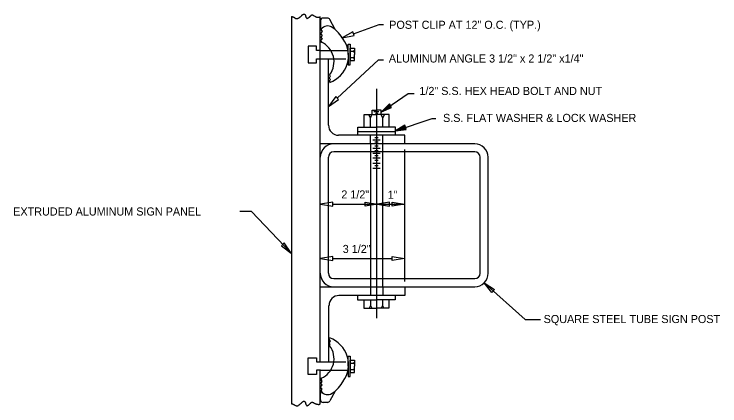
# Model space of a CAD drawing. Extents: x 126.99 to 133.44, y 121.5 to 131.07.
# Drawn here: x 126.99 to 132.24, y 128.16 to 131.07 of the extents above; entities that cross this region are included whole.
import ezdxf

# ---------------------------------------------------------------- set-up
doc = ezdxf.new("R2010")
doc.units = 0
for name, color, linetype in [('DETL-DIMS', 7, 'Continuous'), ('DETL-LINE', 7, 'Continuous'), ('DETL-NOTE', 7, 'Continuous')]:
    doc.layers.add(name, color=color, linetype=linetype)

msp = doc.modelspace()

# ---------------------------------------------------------------- linework, layer by layer
at = {"layer": 'DETL-DIMS'}
for p, q in [((129.5147, 130.9229), (129.7057, 130.9919)), ((129.7057, 130.9919), (129.7367, 130.9919)), ((129.3937, 130.4449), (129.7007, 130.7299)), ((129.7007, 130.7299), (129.7367, 130.7299)), ((129.6847, 130.5129), (129.6847, 128.8109)), ((129.7217, 130.3439), (129.9207, 130.4799)), ((129.9207, 130.4799), (129.9647, 130.4799)), ((129.8257, 130.2029), (130.0997, 130.2929)), ((130.0997, 130.2929), (130.1257, 130.2929)), ((129.8927, 130.0639), (129.8927, 129.0839)), ((129.3597, 129.6575), (129.8927, 129.6575)), ((129.3597, 129.2549), (129.7607, 129.2549)), ((129.7607, 129.2549), (129.8007, 129.2549))]:
    msp.add_line(p, q, dxfattribs=at)
for points in [[(129.5197, 130.9089), (129.5097, 130.9369), (129.4307, 130.8929)], [(129.4037, 130.4339), (129.3827, 130.4559), (129.3277, 130.3829)], [(129.3597, 129.6425), (129.3597, 129.6725), (129.2697, 129.6575)], [(129.6018, 129.6425), (129.6018, 129.6725), (129.6918, 129.6575)], [(129.7818, 129.6425), (129.7818, 129.6725), (129.6918, 129.6575)], [(129.8027, 129.6425), (129.8027, 129.6725), (129.8927, 129.6575)], [(129.0002, 129.3701), (128.9784, 129.3494), (129.0512, 129.2945)], [(129.3597, 129.2399), (129.3597, 129.2699), (129.2697, 129.2549)], [(129.8027, 129.2399), (129.8027, 129.2699), (129.8927, 129.2549)], [(130.5624, 129.0252), (130.5424, 129.0029), (130.4854, 129.0742)]]:
    msp.add_lwpolyline(points, close=True, dxfattribs=at)
for points in [[(129.7807, 130.4019), (129.7217, 130.3439), (129.7977, 130.3759), (129.7807, 130.4019)], [(129.7797, 130.3989), (129.7307, 130.3499), (129.7947, 130.3769), (129.7797, 130.3989)], [(129.7797, 130.3959), (129.7397, 130.3559), (129.7917, 130.3779), (129.7797, 130.3959)], [(129.7797, 130.3929), (129.7477, 130.3609), (129.7887, 130.3789), (129.7797, 130.3929)], [(129.7787, 130.3899), (129.7567, 130.3679), (129.7857, 130.3799), (129.7787, 130.3899)], [(129.7787, 130.3869), (129.7657, 130.3739), (129.7827, 130.3809), (129.7787, 130.3869)], [(129.7787, 130.3839), (129.7747, 130.3799), (129.7797, 130.3809), (129.7787, 130.3839)], [(129.8967, 130.2429), (129.8257, 130.2029), (129.9067, 130.2129), (129.8967, 130.2429)], [(129.8957, 130.2409), (129.8357, 130.2059), (129.9047, 130.2149), (129.8957, 130.2409)], [(129.8957, 130.2369), (129.8457, 130.2099), (129.9017, 130.2159), (129.8957, 130.2369)], [(129.8937, 130.2349), (129.8557, 130.2129), (129.8997, 130.2189), (129.8937, 130.2349)], [(129.8927, 130.2309), (129.8657, 130.2159), (129.8957, 130.2209), (129.8927, 130.2309)], [(129.8917, 130.2289), (129.8757, 130.2199), (129.8937, 130.2219), (129.8917, 130.2289)], [(129.8907, 130.2259), (129.8857, 130.2229), (129.8907, 130.2229), (129.8907, 130.2259)], [(129.0506, 129.295), (128.756, 129.6034), (128.671, 129.6034)], [(130.4854, 129.0742), (130.7888, 128.8012), (130.9022, 128.8012)]]:
    msp.add_lwpolyline(points, dxfattribs=at)
at = {"layer": 'DETL-LINE'}
for p, q in [((129.0527, 131.0499), (129.0527, 128.1759)), ((129.0527, 131.0499), (129.0607, 131.0499)), ((129.0607, 131.0499), (129.0607, 131.0489)), ((129.0607, 131.0489), (129.0637, 131.0489)), ((129.0637, 131.0489), (129.0647, 131.0469)), ((129.0647, 131.0469), (129.0677, 131.0469)), ((129.0677, 131.0469), (129.0687, 131.0459)), ((129.0687, 131.0459), (129.0697, 131.0449)), ((129.0697, 131.0449), (129.0707, 131.0449)), ((129.0707, 131.0449), (129.0727, 131.0449)), ((129.0727, 131.0449), (129.0737, 131.0429)), ((129.0737, 131.0429), (129.0757, 131.0409)), ((129.1097, 131.0409), (129.1107, 131.0429)), ((129.1107, 131.0429), (129.1127, 131.0429)), ((129.1127, 131.0429), (129.1147, 131.0449)), ((129.1147, 131.0449), (129.1157, 131.0449)), ((129.1157, 131.0459), (129.1197, 131.0479)), ((129.1157, 131.0449), (129.1157, 131.0459)), ((129.1197, 131.0479), (129.1207, 131.0499)), ((129.1207, 131.0499), (129.1207, 131.0509)), ((129.1207, 131.0509), (129.1227, 131.0509)), ((129.1227, 131.0509), (129.1267, 131.0559)), ((129.1267, 131.0559), (129.1277, 131.0559)), ((129.1277, 131.0559), (129.1297, 131.0579)), ((129.1297, 131.0579), (129.1307, 131.0599)), ((129.1307, 131.0599), (129.1307, 131.0609)), ((129.1307, 131.0609), (129.1317, 131.0609)), ((129.1317, 131.0609), (129.1327, 131.0619)), ((129.1327, 131.0619), (129.1347, 131.0629)), ((129.1347, 131.0629), (129.1357, 131.0649)), ((129.1357, 131.0649), (129.1377, 131.0659)), ((129.1377, 131.0659), (129.1397, 131.0659)), ((129.1397, 131.0659), (129.1427, 131.0679)), ((129.1427, 131.0679), (129.1437, 131.0679)), ((129.1437, 131.0679), (129.1457, 131.0679)), ((129.1457, 131.0679), (129.1487, 131.0679)), ((129.1487, 131.0679), (129.1497, 131.0679)), ((129.1497, 131.0679), (129.1507, 131.0669)), ((129.1507, 131.0669), (129.1527, 131.0659)), ((129.1527, 131.0659), (129.1537, 131.0649)), ((129.1537, 131.0649), (129.1547, 131.0649)), ((129.1547, 131.0649), (129.1557, 131.0609)), ((129.1557, 131.0609), (129.1577, 131.0599)), ((129.1577, 131.0599), (129.1577, 131.0579)), ((129.1577, 131.0579), (129.1577, 131.0559)), ((129.1577, 131.0559), (129.1577, 131.0549)), ((129.1577, 131.0549), (129.1587, 131.0529)), ((129.1587, 131.0529), (129.1587, 131.0509)), ((129.1587, 131.0509), (129.1597, 131.0509)), ((129.1597, 131.0509), (129.1597, 131.0499)), ((129.1597, 131.0499), (129.1607, 131.0449)), ((129.1607, 131.0449), (129.1607, 131.0449)), ((129.1607, 131.0449), (129.1627, 131.0429)), ((129.1627, 131.0429), (129.1627, 131.0419)), ((129.1627, 131.0419), (129.1647, 131.0399)), ((129.1797, 131.0409), (129.1827, 131.0429)), ((129.1827, 131.0429), (129.1847, 131.0449)), ((129.1847, 131.0449), (129.1857, 131.0459)), ((129.1857, 131.0459), (129.1867, 131.0459)), ((129.1867, 131.0459), (129.1907, 131.0509)), ((129.1907, 131.0509), (129.1917, 131.0509)), ((129.1917, 131.0509), (129.1927, 131.0529)), ((129.1927, 131.0529), (129.1947, 131.0529)), ((129.1947, 131.0529), (129.1957, 131.0549)), ((129.1957, 131.0549), (129.1977, 131.0559)), ((129.1977, 131.0559), (129.2007, 131.0589)), ((129.2007, 131.0609), (129.2057, 131.0619)), ((129.2007, 131.0599), (129.2007, 131.0609)), ((129.2007, 131.0589), (129.2007, 131.0599)), ((129.2057, 131.0619), (129.2097, 131.0619)), ((129.2097, 131.0619), (129.2127, 131.0609)), ((129.2127, 131.0609), (129.2147, 131.0609)), ((129.2147, 131.0609), (129.2147, 131.0599)), ((129.2147, 131.0599), (129.2177, 131.0589)), ((129.2177, 131.0589), (129.2197, 131.0569)), ((129.2197, 131.0569), (129.2207, 131.0559)), ((129.2207, 131.0559), (129.2207, 131.0559)), ((129.2207, 131.0559), (129.2227, 131.0559)), ((129.2227, 131.0559), (129.2277, 131.0529)), ((129.2277, 131.0529), (129.2297, 131.0529)), ((129.2297, 131.0529), (129.2297, 131.0509)), ((129.2297, 131.0509), (129.2307, 131.0509)), ((129.2307, 131.0509), (129.2327, 131.0509)), ((129.2327, 131.0509), (129.2347, 131.0499)), ((129.2347, 131.0499), (129.2357, 131.0499)), ((129.2357, 131.0499), (129.2357, 131.0489)), ((129.2357, 131.0489), (129.2377, 131.0489)), ((129.2377, 131.0489), (129.2387, 131.0469)), ((129.2387, 131.0469), (129.2407, 131.0469)), ((129.2407, 131.0469), (129.2407, 131.0459)), ((129.2407, 131.0459), (129.2507, 131.0459)), ((129.2507, 131.0459), (129.2527, 131.0459)), ((129.2527, 131.0459), (129.2587, 131.0459)), ((129.2587, 131.0459), (129.2607, 131.0459)), ((129.2607, 131.0459), (129.2637, 131.0459)), ((129.2637, 131.0459), (129.2677, 131.0499)), ((129.2677, 128.4879), (129.2677, 131.0499)), ((129.0757, 131.0409), (129.0777, 131.0409)), ((129.0777, 131.0409), (129.0847, 131.0359)), ((129.0847, 131.0359), (129.0857, 131.0359)), ((129.0857, 131.0359), (129.0877, 131.0359)), ((129.0877, 131.0359), (129.0897, 131.0359)), ((129.0897, 131.0359), (129.0907, 131.0349)), ((129.0907, 131.0349), (129.0997, 131.0349)), ((129.0997, 131.0349), (129.0997, 131.0359)), ((129.0997, 131.0359), (129.1007, 131.0359)), ((129.1007, 131.0359), (129.1027, 131.0369)), ((129.1027, 131.0379), (129.1047, 131.0389)), ((129.1027, 131.0369), (129.1027, 131.0379)), ((129.1047, 131.0389), (129.1057, 131.0399)), ((129.1057, 131.0399), (129.1097, 131.0409)), ((129.1647, 131.0399), (129.1657, 131.0389)), ((129.1657, 131.0389), (129.1657, 131.0379)), ((129.1657, 131.0379), (129.1667, 131.0369)), ((129.1667, 131.0369), (129.1687, 131.0359)), ((129.1687, 131.0359), (129.1707, 131.0359)), ((129.1707, 131.0359), (129.1747, 131.0379)), ((129.1747, 131.0379), (129.1757, 131.0389)), ((129.1757, 131.0389), (129.1777, 131.0399)), ((129.1777, 131.0399), (129.1777, 131.0409)), ((129.1777, 131.0409), (129.1797, 131.0409)), ((129.2688, 131.0185), (129.2688, 130.9714)), ((129.3208, 131.0382), (129.289, 131.0385)), ((129.3778, 130.9541), (129.3382, 131.0277)), ((129.2807, 130.9399), (129.2697, 130.9239)), ((129.2703, 130.9639), (129.2738, 130.9553)), ((129.2727, 130.9549), (129.2807, 130.9399)), ((129.2697, 130.9239), (129.2807, 130.9079)), ((129.2807, 130.9079), (129.2707, 130.8959)), ((129.2707, 130.8959), (129.2807, 130.8819)), ((129.2807, 130.8819), (129.2697, 130.8729)), ((129.2697, 130.8729), (129.2787, 130.8659)), ((129.2787, 130.8659), (129.2727, 130.8599)), ((129.4757, 130.8459), (129.4907, 130.8459)), ((129.4757, 130.7689), (129.4757, 130.8459)), ((129.4907, 130.8459), (129.4907, 130.7689)), ((129.1777, 130.8299), (129.1777, 130.7059)), ((129.2397, 130.8299), (129.1777, 130.8299)), ((129.2397, 130.7989), (129.2397, 130.8299)), ((129.2697, 130.7989), (129.2397, 130.7989)), ((129.2697, 130.7989), (129.3507, 130.7989)), ((129.3507, 130.7989), (129.4757, 130.7989)), ((129.4907, 130.8149), (129.5227, 130.8149)), ((129.4907, 130.7689), (129.4907, 130.8149)), ((129.4907, 130.7929), (129.5107, 130.7929)), ((129.4907, 130.7929), (129.5107, 130.7929)), ((129.5107, 130.7929), (129.5217, 130.7999)), ((129.5107, 130.7929), (129.5217, 130.7859)), ((129.5227, 130.8149), (129.5227, 130.7689)), ((129.2397, 130.7359), (129.3647, 130.7359)), ((129.2397, 130.7059), (129.2397, 130.7359)), ((129.3277, 130.2439), (129.3277, 130.7359)), ((129.3647, 130.7359), (129.4577, 130.7359)), ((129.4757, 130.7689), (129.4757, 130.6929)), ((129.4907, 130.6929), (129.4907, 130.7689)), ((129.4907, 130.7689), (129.4907, 130.7229)), ((129.4907, 130.7449), (129.5107, 130.7449)), ((129.4907, 130.7449), (129.5107, 130.7449)), ((129.5107, 130.7449), (129.5217, 130.7509)), ((129.5107, 130.7449), (129.5217, 130.7379)), ((129.5227, 130.7229), (129.5227, 130.7689)), ((129.1777, 130.7059), (129.2397, 130.7059)), ((129.4757, 130.6929), (129.4907, 130.6929)), ((129.4907, 130.7229), (129.5227, 130.7229)), ((129.3427, 130.5829), (129.3327, 130.5729)), ((129.3327, 130.5729), (129.3397, 130.5659)), ((129.3407, 130.6079), (129.3347, 130.5939)), ((129.3347, 130.5939), (129.3427, 130.5829)), ((129.3357, 130.6179), (129.3407, 130.6079)), ((129.3397, 130.5659), (129.3357, 130.5599)), ((129.5927, 130.2299), (129.5927, 130.3229)), ((129.5927, 130.3229), (129.6857, 130.3229)), ((129.6397, 130.2949), (129.6277, 130.3229)), ((129.6397, 130.2949), (129.6507, 130.3229)), ((129.6537, 130.3229), (129.6537, 130.3549)), ((129.6537, 130.3549), (129.6857, 130.3549)), ((129.6657, 130.3449), (129.7027, 130.3449)), ((129.6777, 130.3329), (129.6947, 130.3329)), ((129.7187, 130.3549), (129.6857, 130.3549)), ((129.7797, 130.3229), (129.6857, 130.3229)), ((129.7187, 130.3229), (129.7187, 130.3549)), ((129.7327, 130.2949), (129.7207, 130.3229)), ((129.7327, 130.2949), (129.7437, 130.3229)), ((129.7797, 130.2299), (129.7797, 130.3229)), ((129.6397, 130.2609), (129.6397, 130.2949)), ((129.6397, 130.2299), (129.6397, 130.2609)), ((129.7327, 130.2609), (129.7327, 130.2949)), ((129.7327, 130.2299), (129.7327, 130.2609)), ((129.5457, 130.1689), (129.5457, 130.2299)), ((129.5457, 130.2299), (129.6857, 130.2299)), ((129.8257, 130.2299), (129.6857, 130.2299)), ((129.8257, 130.1689), (129.8257, 130.2299)), ((129.8947, 130.1689), (129.4027, 130.1689)), ((129.5457, 130.1969), (129.8257, 130.1969)), ((129.6397, 130.1069), (129.6397, 130.1689)), ((129.6727, 130.1529), (129.6977, 130.1529)), ((129.7327, 130.1069), (129.7327, 130.1689)), ((129.8947, 130.1069), (129.8947, 130.1689)), ((130.4147, 130.1059), (129.2677, 130.1059)), ((129.6397, 130.1069), (129.6397, 129.0439)), ((129.6577, 130.1359), (129.7127, 130.1359)), ((129.6727, 130.1199), (129.6977, 130.1199)), ((129.7327, 129.0439), (129.7327, 130.1069)), ((130.4147, 130.0459), (129.3677, 130.0459)), ((129.6577, 130.0729), (129.7127, 130.0729)), ((129.6727, 130.0899), (129.6977, 130.0899)), ((129.6727, 130.0549), (129.6977, 130.0549)), ((129.3277, 129.1449), (129.3277, 130.0059)), ((129.6577, 130.0359), (129.7127, 130.0359)), ((129.6577, 130.0009), (129.7127, 130.0009)), ((129.6727, 130.0199), (129.6977, 130.0199)), ((130.4547, 129.1449), (130.4547, 130.0059)), ((130.5147, 129.1449), (130.5147, 130.0059)), ((129.6577, 129.9629), (129.7127, 129.9629)), ((129.6727, 129.9849), (129.6977, 129.9849)), ((129.6727, 129.9449), (129.6977, 129.9449)), ((129.6577, 129.9249), (129.7127, 129.9249)), ((129.3677, 129.1049), (130.4147, 129.1049)), ((129.2677, 129.0449), (130.4147, 129.0449)), ((129.6397, 129.0439), (129.6397, 128.9779)), ((129.7327, 129.0439), (129.7327, 128.9779)), ((129.8947, 129.0449), (129.8947, 128.9799)), ((129.8947, 128.9799), (129.4057, 128.9799)), ((129.5447, 128.9789), (129.5447, 128.9479)), ((129.5447, 128.9479), (129.6847, 128.9479)), ((129.5907, 128.9479), (129.5907, 128.8859)), ((129.6397, 128.9479), (129.6397, 128.9059)), ((129.8247, 128.9479), (129.6847, 128.9479)), ((129.7297, 128.9479), (129.7297, 128.9059)), ((129.7777, 128.9479), (129.7777, 128.8859)), ((129.8247, 128.9789), (129.8247, 128.9479)), ((129.3307, 128.4859), (129.3307, 128.9049)), ((129.6397, 128.9059), (129.6297, 128.8859)), ((129.6397, 128.9059), (129.6497, 128.8859)), ((129.7297, 128.9059), (129.7187, 128.8859)), ((129.7297, 128.9059), (129.7397, 128.8859)), ((129.5907, 128.8859), (129.6847, 128.8859)), ((129.7777, 128.8859), (129.6847, 128.8859)), ((129.3327, 128.6509), (129.3397, 128.6579)), ((129.3427, 128.6409), (129.3327, 128.6509)), ((129.3347, 128.6299), (129.3427, 128.6409)), ((129.3407, 128.6159), (129.3347, 128.6299)), ((129.3397, 128.6579), (129.3357, 128.6649)), ((129.3357, 128.6059), (129.3407, 128.6159)), ((129.4757, 128.5309), (129.4907, 128.5309)), ((129.4757, 128.4549), (129.4757, 128.5309)), ((129.4907, 128.5309), (129.4907, 128.4549)), ((129.1777, 128.3949), (129.1777, 128.5179)), ((129.1777, 128.5179), (129.2397, 128.5179)), ((129.2397, 128.5179), (129.2397, 128.4879)), ((129.2397, 128.4879), (129.3647, 128.4879)), ((129.3647, 128.4879), (129.4577, 128.4879)), ((129.4907, 128.5009), (129.5227, 128.5009)), ((129.4907, 128.4549), (129.4907, 128.5009)), ((129.4907, 128.4789), (129.5107, 128.4789)), ((129.4907, 128.4789), (129.5107, 128.4789)), ((129.5107, 128.4789), (129.5217, 128.4849)), ((129.5107, 128.4789), (129.5217, 128.4729)), ((129.5227, 128.5009), (129.5227, 128.4549)), ((129.2697, 128.4249), (129.2397, 128.4249)), ((129.2397, 128.4249), (129.2397, 128.3949)), ((129.2677, 128.1759), (129.2677, 128.4249)), ((129.2697, 128.4249), (129.3507, 128.4249)), ((129.3507, 128.4249), (129.4757, 128.4249)), ((129.4757, 128.4549), (129.4757, 128.3779)), ((129.4907, 128.3779), (129.4907, 128.4549)), ((129.4907, 128.4549), (129.4907, 128.4089)), ((129.4907, 128.4309), (129.5107, 128.4309)), ((129.4907, 128.4309), (129.5107, 128.4309)), ((129.5107, 128.4309), (129.5217, 128.4369)), ((129.5107, 128.4309), (129.5217, 128.4249)), ((129.5227, 128.4089), (129.5227, 128.4549)), ((129.2397, 128.3949), (129.1777, 128.3949)), ((129.4757, 128.3779), (129.4907, 128.3779)), ((129.4907, 128.4089), (129.5227, 128.4089)), ((129.2697, 128.3509), (129.2787, 128.3559)), ((129.2807, 128.3409), (129.2697, 128.3509)), ((129.2697, 128.2999), (129.2807, 128.3159)), ((129.2707, 128.3279), (129.2807, 128.3409)), ((129.2807, 128.3159), (129.2707, 128.3279)), ((129.2787, 128.3559), (129.2727, 128.3649)), ((129.2807, 128.2849), (129.2697, 128.2999)), ((129.2703, 128.2613), (129.2738, 128.2699)), ((129.2727, 128.2699), (129.2807, 128.2849)), ((129.3778, 128.271), (129.3382, 128.1975)), ((129.2688, 128.2067), (129.2688, 128.2537)), ((129.0527, 128.1759), (129.0607, 128.1759)), ((129.0607, 128.1759), (129.0607, 128.1749)), ((129.0607, 128.1749), (129.0637, 128.1749)), ((129.0637, 128.1749), (129.0647, 128.1729)), ((129.0647, 128.1729), (129.0677, 128.1729)), ((129.0677, 128.1729), (129.0687, 128.1729)), ((129.0687, 128.1729), (129.0697, 128.1709)), ((129.0697, 128.1709), (129.0707, 128.1709)), ((129.0707, 128.1709), (129.0727, 128.1699)), ((129.0727, 128.1699), (129.0737, 128.1689)), ((129.0737, 128.1689), (129.0757, 128.1679)), ((129.0757, 128.1679), (129.0777, 128.1659)), ((129.0777, 128.1659), (129.0847, 128.1629)), ((129.0847, 128.1629), (129.0857, 128.1629)), ((129.0857, 128.1629), (129.0877, 128.1609)), ((129.0877, 128.1609), (129.0897, 128.1609)), ((129.0897, 128.1609), (129.0907, 128.1609)), ((129.0907, 128.1609), (129.0997, 128.1609)), ((129.0997, 128.1609), (129.1007, 128.1609)), ((129.0997, 128.1609), (129.0997, 128.1609)), ((129.1007, 128.1609), (129.1027, 128.1629)), ((129.1027, 128.1639), (129.1047, 128.1649)), ((129.1027, 128.1629), (129.1027, 128.1639)), ((129.1047, 128.1649), (129.1057, 128.1659)), ((129.1057, 128.1659), (129.1097, 128.1679)), ((129.1097, 128.1679), (129.1107, 128.1689)), ((129.1107, 128.1689), (129.1127, 128.1699)), ((129.1127, 128.1699), (129.1147, 128.1709)), ((129.1147, 128.1709), (129.1157, 128.1709)), ((129.1157, 128.1729), (129.1197, 128.1749)), ((129.1157, 128.1709), (129.1157, 128.1729)), ((129.1197, 128.1749), (129.1207, 128.1759)), ((129.1207, 128.1759), (129.1227, 128.1779)), ((129.1207, 128.1759), (129.1207, 128.1759)), ((129.1227, 128.1779), (129.1267, 128.1809)), ((129.1267, 128.1809), (129.1277, 128.1829)), ((129.1277, 128.1829), (129.1297, 128.1839)), ((129.1297, 128.1839), (129.1307, 128.1859)), ((129.1307, 128.1859), (129.1317, 128.1869)), ((129.1307, 128.1859), (129.1307, 128.1859)), ((129.1317, 128.1869), (129.1327, 128.1879)), ((129.1327, 128.1879), (129.1347, 128.1899)), ((129.1347, 128.1899), (129.1357, 128.1909)), ((129.1357, 128.1909), (129.1377, 128.1909)), ((129.1377, 128.1909), (129.1397, 128.1929)), ((129.1397, 128.1929), (129.1427, 128.1949)), ((129.1427, 128.1949), (129.1437, 128.1949)), ((129.1437, 128.1949), (129.1457, 128.1949)), ((129.1457, 128.1949), (129.1487, 128.1949)), ((129.1487, 128.1949), (129.1497, 128.1949)), ((129.1497, 128.1949), (129.1507, 128.1929)), ((129.1507, 128.1929), (129.1527, 128.1909)), ((129.1527, 128.1909), (129.1537, 128.1909)), ((129.1537, 128.1909), (129.1547, 128.1909)), ((129.1547, 128.1909), (129.1557, 128.1859)), ((129.1557, 128.1859), (129.1577, 128.1859)), ((129.1577, 128.1859), (129.1577, 128.1839)), ((129.1577, 128.1839), (129.1577, 128.1829)), ((129.1577, 128.1829), (129.1577, 128.1809)), ((129.1577, 128.1809), (129.1587, 128.1799)), ((129.1587, 128.1799), (129.1587, 128.1779)), ((129.1587, 128.1779), (129.1597, 128.1759)), ((129.1597, 128.1759), (129.1607, 128.1709)), ((129.1597, 128.1759), (129.1597, 128.1759)), ((129.1607, 128.1709), (129.1607, 128.1699)), ((129.1607, 128.1699), (129.1627, 128.1689)), ((129.1627, 128.1689), (129.1627, 128.1679)), ((129.1627, 128.1679), (129.1647, 128.1659)), ((129.1647, 128.1659), (129.1657, 128.1649)), ((129.1657, 128.1649), (129.1657, 128.1639)), ((129.1657, 128.1639), (129.1667, 128.1629)), ((129.1667, 128.1629), (129.1687, 128.1609)), ((129.1687, 128.1609), (129.1707, 128.1609)), ((129.1707, 128.1609), (129.1747, 128.1639)), ((129.1747, 128.1639), (129.1757, 128.1649)), ((129.1757, 128.1649), (129.1777, 128.1659)), ((129.1777, 128.1669), (129.1797, 128.1669)), ((129.1777, 128.1659), (129.1777, 128.1669)), ((129.1797, 128.1669), (129.1827, 128.1699)), ((129.1827, 128.1699), (129.1847, 128.1709)), ((129.1847, 128.1709), (129.1857, 128.1709)), ((129.1857, 128.1709), (129.1867, 128.1729)), ((129.1867, 128.1729), (129.1907, 128.1759)), ((129.1907, 128.1759), (129.1917, 128.1779)), ((129.1917, 128.1779), (129.1927, 128.1789)), ((129.1927, 128.1789), (129.1947, 128.1799)), ((129.1947, 128.1799), (129.1957, 128.1809)), ((129.1957, 128.1809), (129.1977, 128.1819)), ((129.1977, 128.1819), (129.2007, 128.1849)), ((129.2007, 128.1859), (129.2057, 128.1879)), ((129.2007, 128.1859), (129.2007, 128.1859)), ((129.2007, 128.1849), (129.2007, 128.1859)), ((129.2057, 128.1879), (129.2097, 128.1879)), ((129.2097, 128.1879), (129.2127, 128.1869)), ((129.2127, 128.1869), (129.2147, 128.1859)), ((129.2147, 128.1859), (129.2177, 128.1849)), ((129.2147, 128.1859), (129.2147, 128.1859)), ((129.2177, 128.1849), (129.2197, 128.1829)), ((129.2197, 128.1829), (129.2207, 128.1819)), ((129.2207, 128.1819), (129.2207, 128.1809)), ((129.2207, 128.1809), (129.2227, 128.1809)), ((129.2227, 128.1809), (129.2277, 128.1789)), ((129.2277, 128.1789), (129.2297, 128.1789)), ((129.2297, 128.1789), (129.2297, 128.1779)), ((129.2297, 128.1779), (129.2307, 128.1779)), ((129.2307, 128.1779), (129.2327, 128.1759)), ((129.2327, 128.1759), (129.2347, 128.1759)), ((129.2347, 128.1759), (129.2357, 128.1759)), ((129.2357, 128.1759), (129.2357, 128.1749)), ((129.2357, 128.1749), (129.2377, 128.1749)), ((129.2377, 128.1749), (129.2387, 128.1729)), ((129.2387, 128.1729), (129.2407, 128.1729)), ((129.2407, 128.1729), (129.2507, 128.1729)), ((129.2407, 128.1729), (129.2407, 128.1729)), ((129.2507, 128.1729), (129.2527, 128.1709)), ((129.2527, 128.1709), (129.2587, 128.1709)), ((129.2587, 128.1709), (129.2607, 128.1729)), ((129.2607, 128.1729), (129.2637, 128.1729)), ((129.2637, 128.1729), (129.2677, 128.1759)), ((129.3208, 128.187), (129.289, 128.1867))]:
    msp.add_line(p, q, dxfattribs=at)
for centre, radius, start, end in [((129.2888, 131.0185), 0.02, 89.4032, 180), ((129.3206, 131.0182), 0.02, 28.3338, 89.4032), ((129.2888, 130.9714), 0.02, 180, 202.0916), ((129.322, 130.9222), 0.0585, 55.6403, 145.4876), ((129.2513, 130.8009), 0.1987, 40.2149, 60.6793), ((129.2088, 130.7499), 0.2644, 29.2938, 42.7834), ((129.2113, 130.7143), 0.1585, 322.643, 66.6731), ((129.2658, 130.7592), 0.2115, 289.8565, 35.526), ((129.4039, 130.2444), 0.075, 180, 270), ((129.3677, 130.0059), 0.1, 90, 180), ((130.4147, 130.0059), 0.1, 0.0013, 90), ((129.3677, 130.0059), 0.04, 90, 180), ((130.4147, 130.0059), 0.04, 0, 90), ((129.3677, 129.1449), 0.1, 180, 270), ((129.3677, 129.1449), 0.04, 180, 270), ((130.4147, 129.1449), 0.1, 270, 0), ((130.4147, 129.1449), 0.04, 270, 0), ((129.4076, 128.9052), 0.075, 90, 180), ((129.2658, 128.466), 0.2115, 324.474, 70.1435), ((129.2113, 128.5109), 0.1585, 293.3269, 37.357), ((129.2088, 128.4753), 0.2644, 317.2166, 330.7062), ((129.322, 128.303), 0.0585, 214.5124, 304.3597), ((129.2513, 128.4242), 0.1987, 299.3207, 319.7851), ((129.2888, 128.2537), 0.02, 157.9084, 180), ((129.2888, 128.2067), 0.02, 180, 270.5968), ((129.3206, 128.207), 0.02, 270.5968, 331.6662)]:
    msp.add_arc(centre, radius, start, end, dxfattribs=at)

# ---------------------------------------------------------------- texts
at = {"layer": 'DETL-NOTE'}
for s, p in [('POST CLIP AT 12" O.C. (TYP.)', (129.7797, 130.9589)), ('ALUMINUM ANGLE 3 1/2" x 2 1/2" x1/4"', (129.7767, 130.7089)), ('1/2" S.S. HEX HEAD BOLT AND NUT', (130.0037, 130.4679)), ('S.S. FLAT WASHER & LOCK WASHER', (130.1793, 130.2678)), ('2 1/2"', (129.4237, 129.7)), ('1"', (129.7687, 129.6979)), ('EXTRUDED ALUMINUM SIGN PANEL', (126.9872, 129.5733)), ('3 1/2"', (129.4341, 129.2954)), ('SQUARE STEEL TUBE SIGN POST', (130.9265, 128.7754))]:
    msp.add_text(s, height=0.06, dxfattribs=at).set_placement(p)

doc.saveas('drawing.dxf')
